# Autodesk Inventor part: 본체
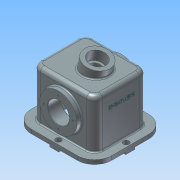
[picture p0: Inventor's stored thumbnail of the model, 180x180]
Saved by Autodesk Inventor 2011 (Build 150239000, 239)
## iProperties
Company: 한국ATC센터
Created: 2014-07
Part Number: 본체
Document SubType Name: Modeling
Designer: KYOUNG IL JANG
Density: 2.71 g/cm^3
Material: 알루미늄-6061
Mass: 2881.56 g
Surface Area: 2079.92 cm^2
Volume: 1063.31 cm^3
Author: KYOUNG IL JANG
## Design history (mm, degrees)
sketch "스케치1"
  geometry: L1 (-76, 65)-(76, 65); L2 (76, 65)-(76, -65); L3 (76, -65)-(-76, -65); L4 (-76, -65)-(-76, 65); 3 further points
  constraints: 8 end point, 2 midpoint, 2 parallel, 1 horizontal, 1 horizontal alignment, 1 perpendicular, 1 vertical alignment
  dimensions: "d0" = 152 distance of L2.end L3.end; "d68" = 130 distance of L3.end L1.start
extrude "돌출1" new body sketch "스케치1" distance "d1" = 128; taper "d2" = 0 deg
fillet "모깎기1" dims "d3" = 20
feature "쉘1" dims "d4" = 10
sketch "스케치2"
  geometry: L1 (-76, 45)-(-76, -45) reference; L2 (56, 65)-(-56, 65) reference; L3 (76, -45)-(76, 45) reference; L4 (-56, -65)-(56, -65) reference; L5 (-98, 45)-(-98, -45); L6 (-56, -87)-(56, -87); L7 (98, -45)-(98, 45); L8 (56, 87)-(-56, 87); A1 r 20 centre (-56, 45) between (-56, 65) and (-76, 45) reference; A2 r 20 centre (-56, -45) between (-76, -45) and (-56, -65) reference; A3 r 20 centre (56, 45) between (76, 45) and (56, 65) reference; A4 r 20 centre (56, -45) between (56, -65) and (76, -45) reference; A5 r 42 centre (-56, 45) between (-56, 87) and (-98, 45); A6 r 42 centre (-56, -45) between (-98, -45) and (-56, -87); A7 r 42 centre (56, -45) between (56, -87) and (98, -45); A8 r 42 centre (56, 45) between (98, 45) and (56, 87); 1 further point
  constraints: 8 end point, 8 point on circle, 4 centre point, 7 other
  dimensions: "d76" = 22 distance between parallel lines of L8 L2
extrude "돌출2" join sketch "스케치2" distance "d9" = 10; taper "d10" = 0 deg
sketch "스케치3"
  geometry: L1 (-65, 0)-(-65, 128) reference; L2 (-55, 0)-(-55, 118) reference; L3 (-77, 68)-(-45, 68); L4 (45, 0)-(-45, 0) reference; L5 (-77, 68)-(-77, 113.5); L6 (-77, 113.5)-(-55, 113.5); L7 (-55, 113.5)-(-45, 103.5); L8 (-45, 103.5)-(-45, 68); 2 further points
  constraints: 10 end point, 4 perpendicular, 1 point on line
  dimensions: "d13" = 68 distance between parallel lines of L3 L4; "d14" = 12 distance from line of L1 L3.start; "d15" = 10 distance from line of L3.end L2; "d16" = 91 diameter of L6 L3; "d17" = 135 deg angle of L7 L2
revolve "회전1" sketch "스케치3" stored, may be unused: angle "d18" = 90 deg
node "작업축2"
sketch "스케치4"
  geometry: C1 r 45.5 at (0, 0) reference; 2 further points
  constraints: 1 vertical alignment
  dimensions: "d19" = 35 distance of C1.centre point (0, 35)
hole "구멍1" sketch "스케치4" at (0, 35) diameter "d20" = 3.459; stored, may be unused: countersink angle "d24" = 90 deg, drill point angle "d26" = 118 deg; dims "d21" = 13, "d22" = 4, "d23" = 2, "d25" = 16
sketch "스케치8"
  geometry: L1 (0, 68)-(-17.88, 152.121); L2 (12.442, 158.566)-(-17.88, 152.121); L3 (-48.203, 145.675)-(-41.706, 115.109); L4 (-41.706, 115.109)-(-11.383, 121.555); L5 (18.939, 128)-(12.442, 158.566); L6 (56, 128)-(-56, 128) reference; L7 (-17.88, 152.121)-(-48.203, 145.675); L8 (-11.383, 121.555)-(18.939, 128); 1 further point
  constraints: 14 end point, 5 parallel, 4 perpendicular, 2 point on line, 1 collinear
  dimensions: "d81" = 12 deg dimension on L1.start L1.end point (0, 0); "d83" = 86 distance from line of L2 L1.start; "d87" = 62 diameter of L5 L1
revolve "회전2" sketch "스케치8" stored, may be unused: angle "d88" = 90 deg
feature "면 삭제1"
hole "구멍2" diameter "d33" = 52; stored, may be unused: countersink angle "d37" = 90 deg, drill point angle "d39" = 118 deg; dims "d31" = 10, "d32" = 10, "d34" = 13, "d35" = 4, "d36" = 2, "d38" = 16
chamfer "모따기1" distance "d55" = 1; stored, may be unused: second distance "d56" = 2, angle "d57" = 45 deg
fillet "모깎기4" dims "d53" = 3
fillet "모깎기2" dims "d30" = 3
sketch "스케치6"
  geometry: 2 further points
  constraints: 1 vertical alignment, 1 other
  dimensions: "d78" = 92 distance of point (0, 0) point (0, 92)
feature "엠보싱3" sketch "스케치6" dims "d0" = 152, "d68" = 130, "d79" = 1, "d80" = 0
fillet "모깎기6" dims "d74" = 10
hole "구멍4" diameter "d91" = 30; stored, may be unused: countersink angle "d95" = 90 deg, drill point angle "d97" = 118 deg; dims "d89" = 10, "d90" = 10, "d92" = 6, "d93" = 42, "d94" = 25, "d96" = 8
fillet "모깎기7" dims "d98" = 3
fillet "모깎기8" dims "d99" = 0.3
sketch "스케치10"
  geometry: L1 (-98, -45)-(-98, 45) reference; L2 (-56, 87)-(56, 87) reference; L3 (98, 45)-(98, -45) reference; L4 (56, -87)-(-56, -87) reference; 5 further points
  constraints: 2 horizontal alignment, 2 vertical alignment
  dimensions: "d103" = 10 distance from line of point (-88, 0) L1; "d104" = 10 distance from line of point (0, 77) L2 (= d103); "d105" = 10 distance from line of point (88, 0) L3 (= d103); "d106" = 10 distance from line of point (0, -77) L4 (= d103)
hole "구멍5" sketch "스케치10" at (-88, 0), (88, 0), (0, 77), (0, -77) diameter "d107" = 9; stored, may be unused: countersink angle "d111" = 90 deg, drill point angle "d113" = 118 deg; dims "d108" = 6, "d109" = 14, "d110" = 8.6, "d112" = 8
sketch "스케치11"
  geometry: L1 (98, -11)-(78, -11); L2 (78, -11)-(78, 11); L3 (78, 11)-(98, 11); L4 (98, 11)-(98, -11); L5 (11, 67)-(-11, 67); L6 (-11, 67)-(-11, 87); L7 (-11, 87)-(11, 87); L8 (11, 87)-(11, 67); L9 (-78, -11)-(-98, -11); L10 (-98, -11)-(-98, 11); L11 (-98, 11)-(-78, 11); L12 (-78, 11)-(-78, -11); L13 (11, -87)-(-11, -87); L14 (-11, -87)-(-11, -67); L15 (-11, -67)-(11, -67); L16 (11, -67)-(11, -87); L17 (-56, 87)-(56, 87) reference; L18 (-98, -45)-(-98, 45) reference; L19 (98, 45)-(98, -45) reference; L20 (56, -87)-(-56, -87) reference; C1 r 4.5 at (88, 0) reference; C2 r 4.5 at (0, 77) reference; C3 r 4.5 at (-88, 0) reference; C4 r 4.5 at (0, -77) reference; 9 further points
  constraints: 32 end point, 8 midpoint, 8 parallel, 4 collinear, 4 horizontal, 4 horizontal alignment, 4 perpendicular, 4 vertical alignment, 3 equal length
  dimensions: "d114" = 22 distance of L3.end L1.start
extrude "돌출8" join sketch "스케치11" distance "d115" = 5; taper "d116" = 0 deg
node "솔리드1" dims "d16" = 91
pattern_circular "원형 패턴1" dims angle "d28" = 360 deg
mirror "대칭3"
